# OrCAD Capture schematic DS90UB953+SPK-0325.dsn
size C; title: Subboard; rev: 0.1; note: DS90UB953
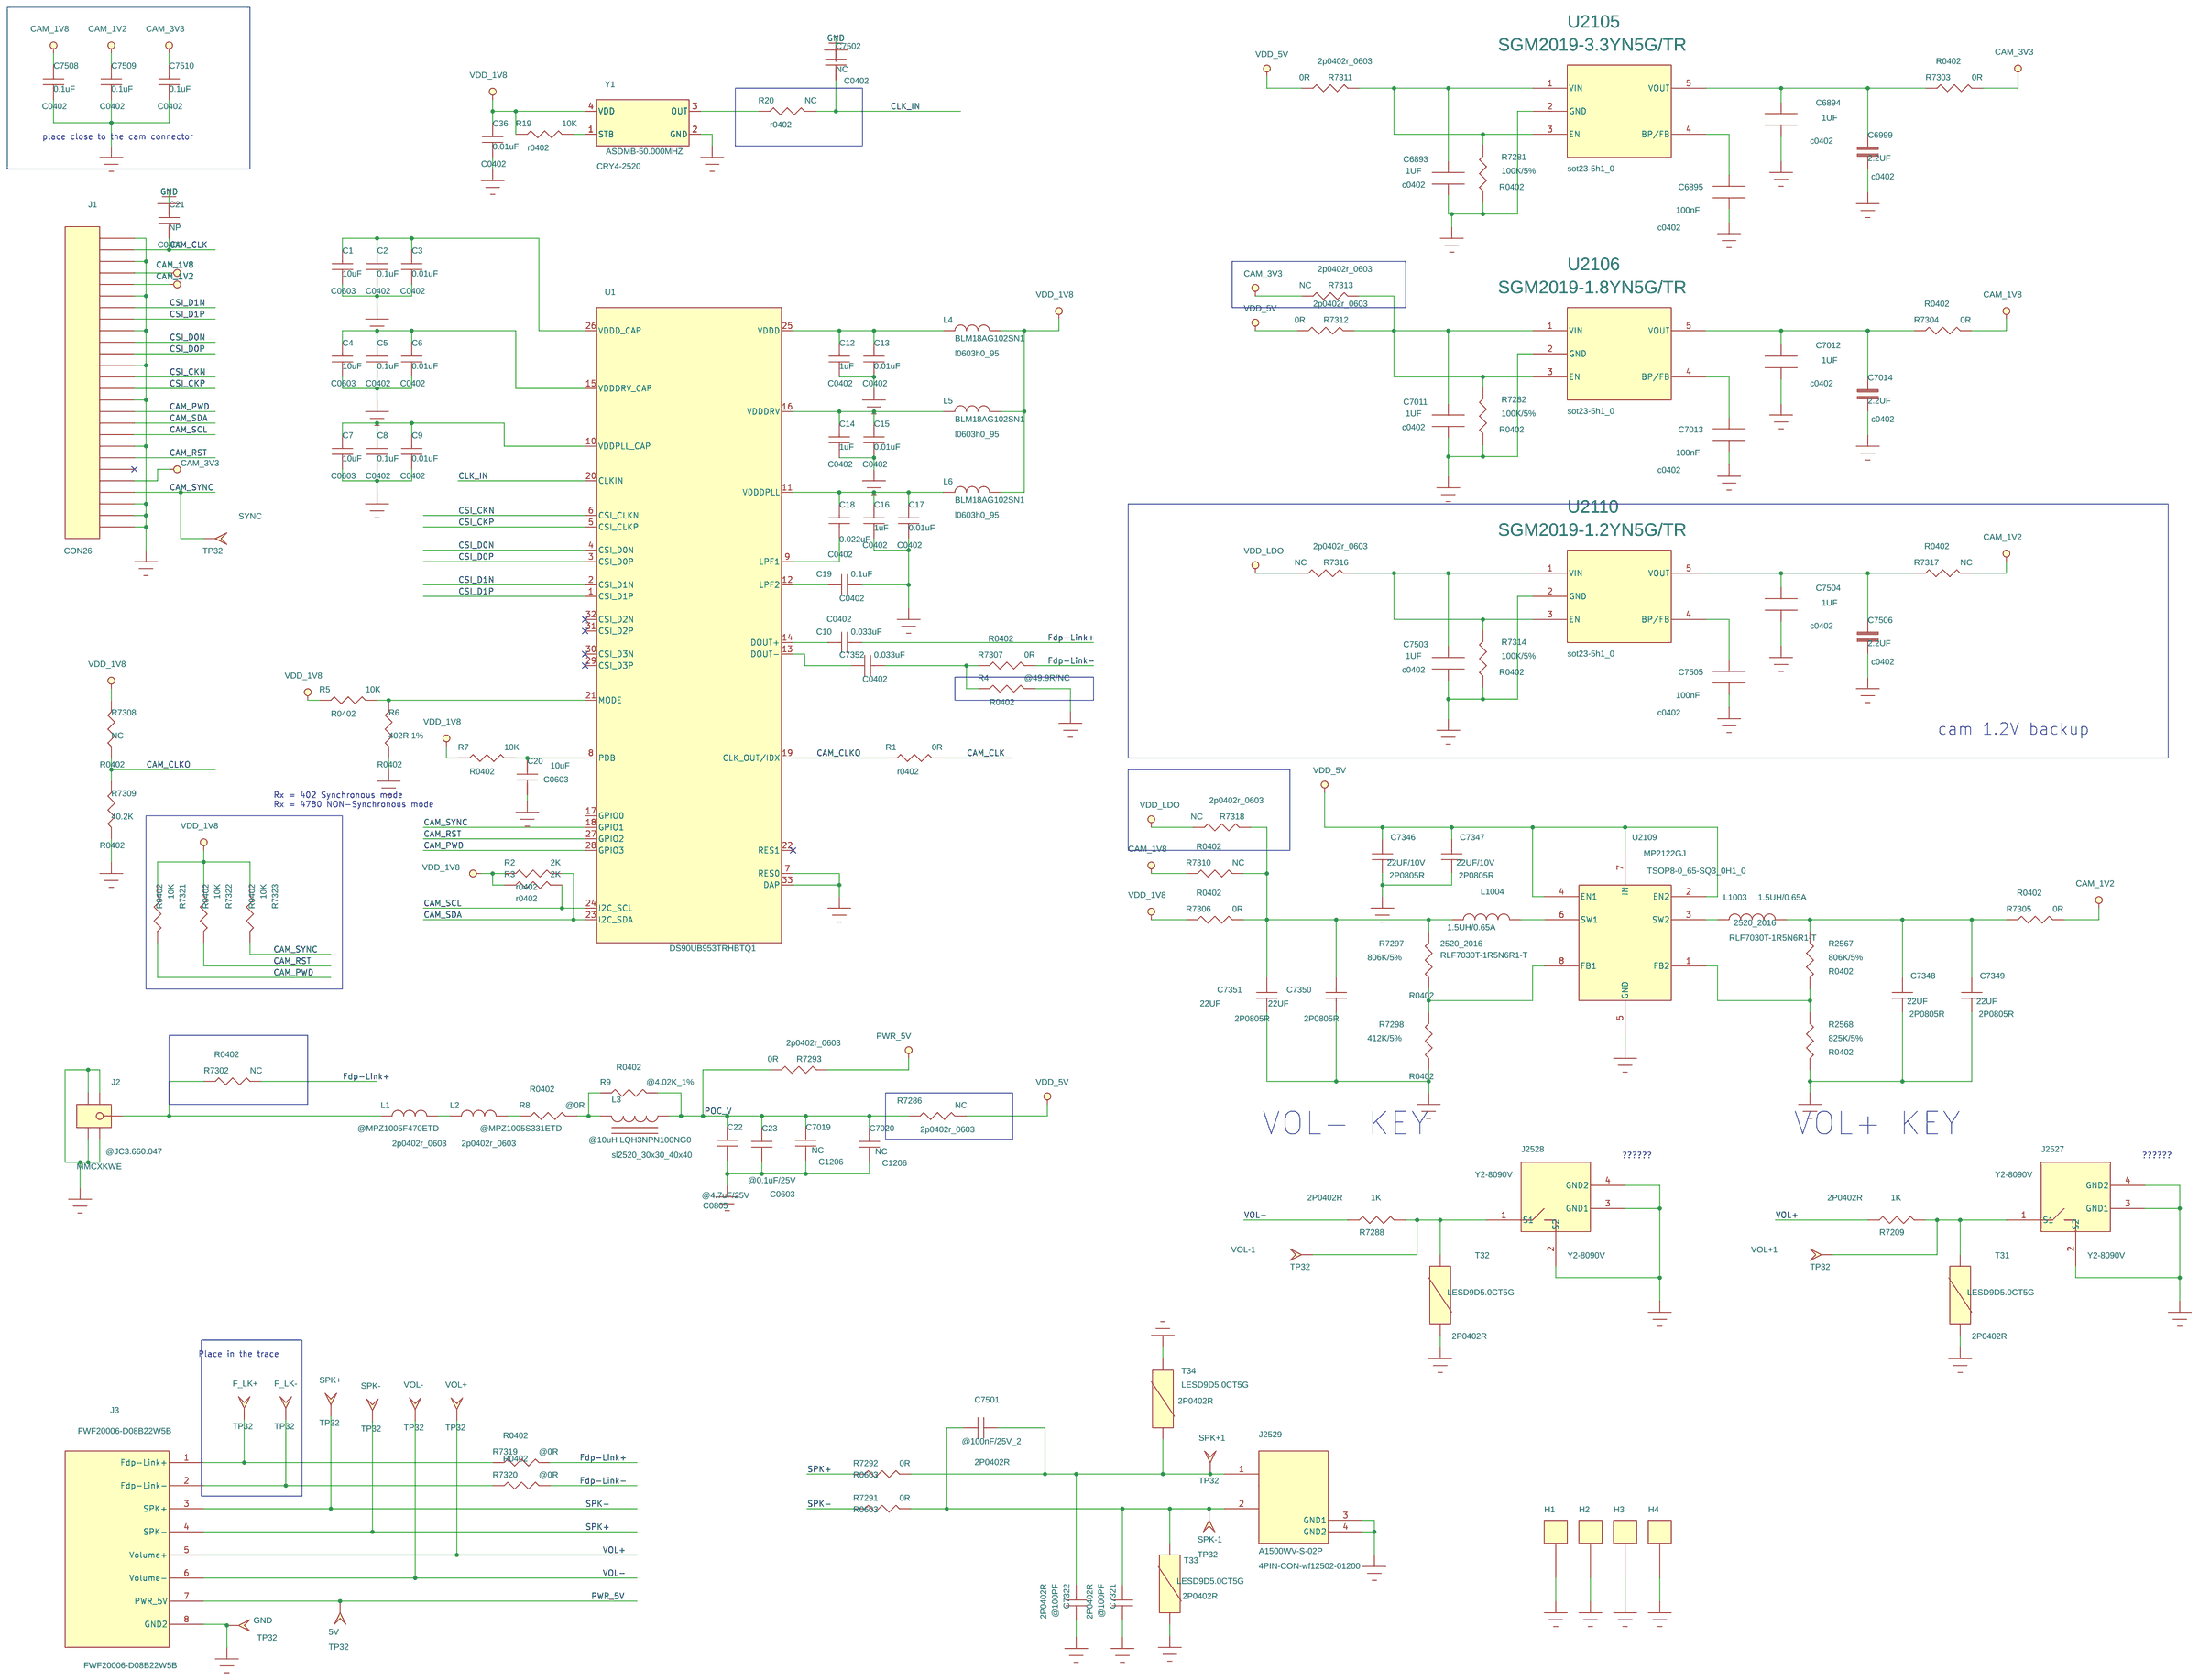
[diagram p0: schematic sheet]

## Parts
5V  DNI(TP1_3)  [TP32]
C1  10uF  [C0603]
C2  0.1uF  [C0402]
C3  0.01uF  [C0402]
C4  10uF  [C0603]
C5  0.1uF  [C0402]
C6  0.01uF  [C0402]
C7  10uF  [C0603]
C8  0.1uF  [C0402]
C9  0.01uF  [C0402]
C10  0.033uF  [C0402]
C12  1uF  [C0402]
C13  0.01uF  [C0402]
C14  1uF  [C0402]
C15  0.01uF  [C0402]
C16  1uF  [C0402]
C17  0.01uF  [C0402]
C18  0.022uF  [C0402]
C19  0.1uF  [C0402]
C20  10uF  [C0603]
C21  NP  [C0402]
C22  @4.7uF/25V  [C0805]
C23  @0.1uF/25V  [C0603]
C36  0.01uF  [C0402]
C6893  1UF  [c0402]
C6894  1UF  [c0402]
C6895  100nF  [c0402]
C6999  2.2UF  [c0402]
C7011  1UF  [c0402]
C7012  1UF  [c0402]
C7013  100nF  [c0402]
C7014  2.2UF  [c0402]
C7019  NC  [C1206]
C7020  NC  [C1206]
C7321  @100PF  [2P0402R]
C7322  @100PF  [2P0402R]
C7346  22UF/10V  [2P0805R]
C7347  22UF/10V  [2P0805R]
C7348  22UF  [2P0805R]
C7349  22UF  [2P0805R]
C7350  22UF  [2P0805R]
C7351  22UF  [2P0805R]
C7352  0.033uF  [C0402]
C7501  @100nF/25V_2  [2P0402R]
C7502  NC  [C0402]
C7503  1UF  [c0402]
C7504  1UF  [c0402]
C7505  100nF  [c0402]
C7506  2.2UF  [c0402]
C7508  0.1uF  [C0402]
C7509  0.1uF  [C0402]
C7510  0.1uF  [C0402]
F_LK+  DNI(TP1_3)  [TP32]
F_LK-  DNI(TP1_3)  [TP32]
GND  DNI(TP1_3)  [TP32]
H1  HOLE1  [Hole4p0cir2p1]
H2  HOLE1  [Hole4p0cir2p1]
H3  HOLE1  [Hole4p0cir2p1]
H4  HOLE1  [Hole4p0cir2p1]
J1  CON26  [fpc0520d-m24-00rw]
J2  @JC3.660.047  [MMCXKWE]
J3  FWF20006-D08B22W5B  [FWF20006-D08B22W5B]
J2527  Y2-8090V  [Y2-8090V]
J2528  Y2-8090V  [Y2-8090V]
J2529  A1500WV-S-02P  [4PIN-CON-wf12502-01200]
L1  @MPZ1005F470ETD  [2p0402r_0603]
L2  @MPZ1005S331ETD  [2p0402r_0603]
L3  @10uH LQH3NPN100NG0  [sl2520_30x30_40x40]
L4  BLM18AG102SN1  [l0603h0_95]
L5  BLM18AG102SN1  [l0603h0_95]
L6  BLM18AG102SN1  [l0603h0_95]
L1003  1.5UH/0.65A  [2520_2016]
L1004  1.5UH/0.65A  [2520_2016]
R1  0R  [r0402]
R2  2K  [r0402]
R3  2K  [r0402]
R4  @49.9R/NC  [R0402]
R5  10K  [R0402]
R6  402R 1%  [R0402]
R7  10K  [R0402]
R8  @0R  [R0402]
R9  @4.02K_1%  [R0402]
R19  10K  [r0402]
R20  NC  [r0402]
R2567  806K/5%  [R0402]
R2568  825K/5%  [R0402]
R7209  1K  [2P0402R]
R7281  100K/5%  [R0402]
R7282  100K/5%  [R0402]
R7286  NC  [2p0402r_0603]
R7288  1K  [2P0402R]
R7291  0R  [R0603]
R7292  0R  [R0603]
R7293  0R  [2p0402r_0603]
R7297  806K/5%  [R0402]
R7298  412K/5%  [R0402]
R7302  NC  [R0402]
R7303  0R  [R0402]
R7304  0R  [R0402]
R7305  0R  [R0402]
R7306  0R  [R0402]
R7307  0R  [R0402]
R7308  NC  [R0402]
R7309  40.2K  [R0402]
R7310  NC  [R0402]
R7311  0R  [2p0402r_0603]
R7312  0R  [2p0402r_0603]
R7313  NC  [2p0402r_0603]
R7314  100K/5%  [R0402]
R7316  NC  [2p0402r_0603]
R7317  NC  [R0402]
R7318  NC  [2p0402r_0603]
R7319  @0R  [R0402]
R7320  @0R  [R0402]
R7321  10K  [R0402]
R7322  10K  [R0402]
R7323  10K  [R0402]
SPK+  DNI(TP1_3)  [TP32]
SPK+1  DNI(TP1_3)  [TP32]
SPK-  DNI(TP1_3)  [TP32]
SPK-1  DNI(TP1_3)  [TP32]
SYNC  DNI(TP1_3)  [TP32]
T31  LESD9D5.0CT5G  [2P0402R]
T32  LESD9D5.0CT5G  [2P0402R]
T33  LESD9D5.0CT5G  [2P0402R]
T34  LESD9D5.0CT5G  [2P0402R]
U1  DS90UB953TRHBTQ1  [QFN32-0_5-SQ5H0_85]
U2105  SGM2019-3.3YN5G/TR  [sot23-5h1_0]
U2106  SGM2019-1.8YN5G/TR  [sot23-5h1_0]
U2109  MP2122GJ  [TSOP8-0_65-SQ3_0H1_0]
U2110  SGM2019-1.2YN5G/TR  [sot23-5h1_0]
VOL+  DNI(TP1_3)  [TP32]
VOL+1  DNI(TP1_3)  [TP32]
VOL-  DNI(TP1_3)  [TP32]
VOL-1  DNI(TP1_3)  [TP32]
Y1  ASDMB-50.000MHZ  [CRY4-2520]

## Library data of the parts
5V F_LK+ F_LK- GND SPK+ SPK+1 SPK- SPK-1 SYNC VOL+ VOL+1 VOL- VOL-1 = TP: Created by/Date: QIANQIU.LI/2013/04/17; Height: 0.01MM; MCN: NA; Manufacturer: NA; Manufacturer Part Number: TP-1_3; Part Number: TESTPOINT1_3; Part Type: MISC
C1-C10 C12-C23 C36 C7019 C7020 C7352 C7502 C7508-C7510 = CAP_NP
C6893 C6894 C7011 C7012 C7503 C7504 = CAP_NP_1: CAP-1UF,+80%,-20%,6.3V-0402; MCN: 105-35092-2105; Manufacturer: MURATA; Manufacturer Part Number: GRM155F50J105ZE01D; Part Number: GRM155F50J105ZE01D; Part Type: CAPACITOR; Tolerance: +80%,-20%; Voltage: 6.3V; Datasheet: M:\CAD\Lib\SPECA\DISCRETE\RLC\MURATA-GRM-ROHS.PDF
C6895 C7013 C7505 = CAP_NP_0: CAP-100NF,+/-10%,6.3V-0201; MCN: 105-35092-2105; Manufacturer: MURATA; Manufacturer Part Number: GRM155F50J105ZE01D; Part Number: GRM155F50J105ZE01D; Part Type: CAPACITOR; Tolerance: +80%,-20%; Voltage: 6.3V; Datasheet: M:\CAD\Lib\SPECA\DISCRETE\RLC\MURATA-GRM-ROHS.PDF
C6999 C7014 C7506 = 0402C-47p_1: TN: 207-0140-000
C7321 C7322 C7501 = CAP_NP: CAP-100PF,+/-5%,50V-0201; Allegro PCB Footprint: 2P0201R; Area: 0.18; Category: PMIC CODEC; Group: Audio Passives; Height: 0.33MM; MCN: 105-35067-1101; Manufacturer: MURATA; Manufacturer Part Number: GRM0335C1H101JA01D; Part Number: GRM0335C1H101JA01D; Part Type: CAPACITOR; SIGNAL_MODEL: DEFAULT_CAPACITOR_0.001pF_1_2; Subsystem: Audio; Tolerance: +/-5%; Voltage: 50V; X size: 0.6; Y size: 0.3; Datasheet: M:\CAD\Lib\SPECA\DISCRETE\RLC\MURATA-GRM-ROHS.PDF
C7346-C7351 = CAP_NP: CAP-0.1UF,+/-10%,10V-0402; Height: 0.56MM; MCN: 105-35273-2104; Manufacturer: MURATA; Manufacturer Part Number: GRM155R61A104KA01D; Part Number: GRM155R61A104KA01D; Part Type: CAPACITOR; Tolerance: +/-10%; Voltage: 10V; Datasheet: M:\CAD\Lib\SPECA\DISCRETE\RLC\MURATA-GRM-ROHS.PDF
H1-H4 = HEADER_1_0
J1 = CON26
J2 = BNC_0
J3 = CONN_6_M4_SIMCARD_7: CONN,SIM CARD 6-POSITION 1.50MM; Created by/Date: QIANQIU.LI/2013/03/28; Height: 1.70MM; MCN: 470-72186-0150; Manufacturer: EVERWIN; Manufacturer Part Number: SIMF006M5K36-OOR; Part Number: SIMF006M5K36-OOR; Part Type: CONNECTOR; Datasheet: M:\CAD\LIB\SPECA\CONNECTOR\SIM CONN\SIMF006M5K36-OOR.PDF
J2527 J2528 = TS-022_1
J2529 = TS-022_0
L1 L2 L4-L6 = INDUCTOR_0
L3 = INDUCTOR_IRON
L1003 L1004 = INDUCTOR: INDUCTOR,POWER 1.0UH 20% 2.7A 0.037OHM SHIELDED; Created by/Date: YIXIAN.HU/2013/04/03; First Project: QRD9225; Height: 1.20MM; MCN: 110-67469-01R0; Manufacturer: CYNTEC; Manufacturer Part Number: SPH252012H1R5MT; Part Number: RLF7030T-1R5N6R1-T; Tolerance: +/-20%; Datasheet: M:\CAD\LIB\SPECA\DISCRETE\RLC\PSE25201B.PDF
R1-R9 R19 R20 R7286 R7291-R7293 R7302-R7313 R7316-R7323 = R
R2567 R2568 R7281 R7282 R7297 R7298 R7314 = R_6: RES-0R,5%,1/20W-0201; Height: 0.30MM; MCN: 100-46311-0000; Manufacturer: WALSIN TECHNOLOGY; Manufacturer Part Number: WR02X000JAL; Part Number: WR02X000 JAL_1; Part Type: RESISTOR; Tolerance: 5%; Voltage: 1/20W
R7209 R7288 = R_6: RES-0R,5%,1/16W-0402; Height: 0.40MM; MCN: 100-46312-0000; Manufacturer: WALSIN TECHNOLOGY; Manufacturer Part Number: WR04X000PTL; Part Number: WR04X000 PTL; Part Type: RESISTOR; Tolerance: 5%; Voltage: 1/16W
T31-T34 = GCDIODE_ESD: GCDIODE ESD SUPPRESSORS; Created by/Date: LISA.YUE/2011/11/19; Height: 0.61MM; MCN: 328-69765-0000; Manufacturer: AEM; Manufacturer Part Number: ES0402V014CT-GT; Part Number: ES0402V014CT-GT_1; Part Type: MISC; Datasheet: M:\CAD\Lib\SPECA\DISCRETE\ESD\ES0402V014CT-GT.PDF
U1 = ds90ub953-q1
U2105 U2106 U2110 = TPS22902_1: 3.3V LDO SOT23-5; Created by/Date: yuling/2012/06/07; MCN: 287-69838-0001; Manufacturer: TI; Manufacturer Part Number: TPS22902BYFPR; Part Number: TPS22902BYFPR; Part Type: IC
U2109 = SW_SPST_1: SWITCH,PUSH-BUTTON DC12V 20MA; Created by/Date: QIANQIU.LI/2013/03/28; Height: 1.85MM; MCN: 305-69179-0000; Manufacturer: CITIZEN; Manufacturer Part Number: LS10N2T; Part Number: LS10N2T; Part Type: MISC; Datasheet: M:\CAD\Lib\SPECA\CONNECTOR\SIDE_SWITCH\LS10N2.PDF
Y1 = ASDMB-50.000MHZ

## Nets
GND: C1.2 C2.2 C3.2 C4.2 C5.2 C6.2 C7.2 C8.2 C9.2 C12.2 C13.2 C14.2 C15.2 C16.2 C17.2 C19.2 C20.2 C21.1 C22.2 C23.2 C36.2 C6893.1 C6894.1 C6895.1 C6999.2 C7011.1 C7012.1 C7013.1 C7014.2 C7019.2 C7020.2 C7321.1 C7322.1 C7346.1 C7347.1 C7348.1 C7349.1 C7350.1 C7351.1 C7502.1 C7503.1 C7504.1 C7505.1 C7506.2 C7508.2 C7509.2 C7510.2 GND.1(TP) H1.1 H2.1 H3.1 H4.1 J1.1 J1.3 J1.6 J1.9 J1.12 J1.15 J1.19 J1.24 J1.25 J1.26 J2.2 J2.3 J2.4 J2.5 J3.8(GND2) J2527.2(S2) J2527.3(GND1) J2527.4(GND2) J2528.2(S2) J2528.3(GND1) J2528.4(GND2) J2529.3(GND1) J2529.4(GND2) R4.2 R6.1 R2568.1 R7281.2 R7282.2 R7298.1 R7309.1 R7314.2 T31.2 T32.2 T33.2 T34.2 U1.7(RES0) U1.33(DAP) U2105.2(GND) U2106.2(GND) U2109.5(GND) U2110.2(GND) Y1.2(GND)
VDD_1V8: C36.1 L4.2 L5.2 L6.2 R2.1 R3.1 R5.1 R7.1 R19.1 R7306.1 R7308.2 R7321.1 R7322.1 R7323.1 Y1.4(VDD)
VDD_5V: C7346.2 C7347.2 R7286.2 R7311.2 R7312.2 U2109.2(EN2) U2109.4(EN1) U2109.7(IN)
VDD_LDO: R7316.2 R7318.2
CAM_1V2: C7509.1 J1.5 R7305.2 R7317.2
CAM_1V8: C7508.1 J1.4 R7304.2 R7310.1
CAM_3V3: C7510.1 J1.22 R7303.2 R7313.2
CAM_CLK: C21.2 J1.2 R1.2
CAM_CLKO: R1.1 R7308.1 R7309.2 U1.19(CLK_OUT/IDX)
CAM_PWD: J1.16 R7321.2 U1.28(GPIO3)
CAM_RST: J1.20 R7322.2 U1.27(GPIO2)
CAM_SCL: J1.18 R3.2 U1.24(I2C_SCL)
CAM_SDA: J1.17 R2.2 U1.23(I2C_SDA)
CAM_SYNC: J1.23 R7323.2 SYNC.1(TP) U1.18(GPIO1)
CLK_IN: C7502.2 R20.2 U1.20(CLKIN)
CSI_CKN: J1.13 U1.6(CSI_CLKN)
CSI_CKP: J1.14 U1.5(CSI_CLKP)
CSI_D0N: J1.10 U1.4(CSI_D0N)
CSI_D0P: J1.11 U1.3(CSI_D0P)
CSI_D1N: J1.7 U1.2(CSI_D1N)
CSI_D1P: J1.8 U1.1(CSI_D1P)
Fdp-Link+: C10.2 R7302.2 R7319.2
Fdp-Link-: R7307.2 R7320.2
POC_V: C22.1 C23.1 C7019.1 C7020.1 L3.1 R9.2 R7286.1 R7293.2
PWR_5V: 5V.1(TP) J3.7(PWR_5V) R7293.1
SPK+: J3.4(SPK-) R7292.1 SPK-.1(TP)
SPK-: J3.3(SPK+) R7291.1 SPK+.1(TP)
VOL+: J3.5(Volume+) R7209.1 VOL+.1(TP)
VOL-: J3.6(Volume-) R7288.1 VOL-.1(TP)
N00294: C1.1 C2.1 C3.1 U1.26(VDDD_CAP)
N00623: C4.1 C5.1 C6.1 U1.15(VDDDRV_CAP)
N01072: C7.1 C8.1 C9.1 U1.10(VDDPLL_CAP)
N03572: C10.1 U1.14(DOUT+)
N03592: C7352.1 U1.13(DOUT-)
N03606: J2.1 L1.1 R7302.1
N03646: C7352.2 R4.1 R7307.1
N04688: C12.1 C13.1 L4.1 U1.25(VDDD)
N05216: C14.1 C15.1 L5.1 U1.16(VDDDRV)
N05348: C16.1 C17.1 C18.1 L6.1 U1.11(VDDDPLL)
N05546: C18.2 U1.9(LPF1)
N05630: C19.1 U1.12(LPF2)
N08569: R5.2 R6.2 U1.21(MODE)
N08620: C20.1 R7.2 U1.8(PDB)
N10872: L1.2 L2.1
N10876: L2.2 R8.1
N10907: L3.2 R8.2 R9.1
N20067: R19.2 Y1.1(STB)
N20534: R20.1 Y1.3(OUT)
N40133: C6893.2 R7281.1 R7311.1 U2105.1(VIN) U2105.3(EN)
N40219: C6895.2 U2105.4(BP/FB)
N40223: C6894.2 C6999.1 R7303.1 U2105.5(VOUT)
N40778: C7011.2 R7282.1 R7312.1 R7313.1 U2106.1(VIN) U2106.3(EN)
N40864: C7013.2 U2106.4(BP/FB)
N40868: C7012.2 C7014.1 R7304.1 U2106.5(VOUT)
N92182: J2527.1(S1) R7209.2 T31.1 VOL+1.1(TP)
N92991: J2528.1(S1) R7288.2 T32.1 VOL-1.1(TP)
N121438: L1003.1 U2109.3(SW2)
N121471: R2567.1 R2568.2 U2109.1(FB2)
N121478: C7348.2 C7349.2 L1003.2 R2567.2 R7305.1
N129833: R7297.1 R7298.2 U2109.8(FB1)
N129837: C7350.2 C7351.2 L1004.2 R7297.2 R7306.2 R7310.2 R7318.1
N131151: L1004.1 U2109.6(SW1)
N133411: C7322.2 C7501.1 J2529.1 R7292.2 SPK+1.1(TP) T34.1
N133415: C7321.2 C7501.2 J2529.2 R7291.2 SPK-1.1(TP) T33.1
N134026: F_LK+.1(TP) J3.1(Fdp-Link+) R7319.1
N134032: F_LK-.1(TP) J3.2(Fdp-Link-) R7320.1
N180611: C7503.2 R7314.1 R7316.1 U2110.1(VIN) U2110.3(EN)
N180695: C7504.2 C7506.1 R7317.1 U2110.5(VOUT)
N180699: C7505.2 U2110.4(BP/FB)

Not connected (* = marked no-connect by the designer): J1 21*; U1 17(GPIO0) 22(RES1)* 29(CSI_D3P)* 30(CSI_D3N)* 31(CSI_D2P)* 32(CSI_D2N)*

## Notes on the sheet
- place close to the cam connector
- cam 1.2V backup
- Rx = 402 Synchronous mode
  Rx = 4780 NON-Synchronous mode
- VOL- KEY
- VOL+ KEY
- ??????
- ??????
- Place in the trace
